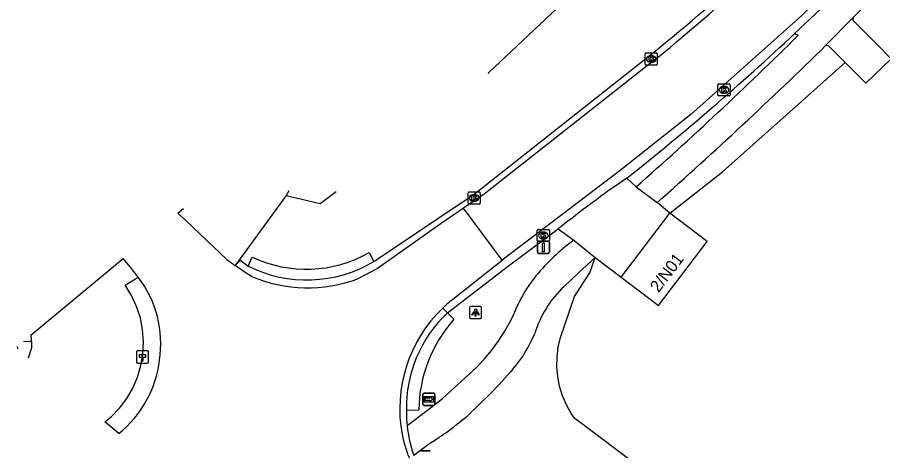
# Model space of a CAD drawing. Extents: x 152881 to 155736, y 382924 to 386919.
# Drawn here: x 152881.3 to 152953.1, y 384938.2 to 384974.1 of the extents above; entities that cross this region are included whole.
import ezdxf

# ---------------------------------------------------------------- set-up
doc = ezdxf.new("R2010")
doc.units = 0
for name, color, linetype in [('IMGEO_Berm_gesloten', 7, 'Continuous'), ('IMGEO_Fietspad_gesloten', 7, 'Continuous'), ('IMGEO_Greppel_droge_sloot', 7, 'Continuous'), ('IMGEO_Groenvoorziening', 7, 'Continuous'), ('IMGEO_Hectometerpaal', 7, 'Continuous'), ('IMGEO_Inrit_open', 7, 'Continuous'), ('IMGEO_Kolk', 7, 'Continuous'), ('IMGEO_Lichtpunt', 7, 'Continuous'), ('IMGEO_Pand', 7, 'Continuous'), ('IMGEO_Pand_nummerreeks', 7, 'Continuous'), ('IMGEO_Rijbaan_lokaal_gesloten', 7, 'Continuous'), ('IMGEO_Rijbaan_lokaal_open', 7, 'Continuous'), ('IMGEO_Sloot', 7, 'Continuous'), ('IMGEO_Verkeersbordpaal', 7, 'Continuous'), ('IMGEO_Wegwijzer', 7, 'Continuous')]:
    doc.layers.add(name, color=color, linetype=linetype)

msp = doc.modelspace()

# ---------------------------------------------------------------- linework, layer by layer
at = {"layer": 'IMGEO_Berm_gesloten'}
for points in [[(152900.494, 384953.465), (152900.84, 384954.217)], [(152910.53, 384954.589), (152910.924, 384953.841)], [(152888.603, 384940.547), (152889.126, 384940.972), (152889.82, 384941.69), (152890.423, 384942.486), (152890.927, 384943.349), (152891.323, 384944.265), (152891.606, 384945.223), (152891.773, 384946.207), (152891.82, 384947.205), (152891.748, 384948.201), (152891.557, 384949.181), (152891.25, 384950.131), (152890.831, 384951.037), (152890.306, 384951.887), (152891.382, 384952.553)], [(152917.573, 384949.062), (152917.038, 384949.591)], [(152913.634, 384941.518), (152914.659, 384941.539)], [(152889.767, 384939.575), (152888.603, 384940.547)]]:
    msp.add_lwpolyline(points, dxfattribs=at)
for centre, radius, start, end in [((152905.327, 384963.724), 10.513, 244.7338, 299.66322), ((152926.146, 384941.415), 11.488, 138.26968, 179.38302)]:
    msp.add_arc(centre, radius, start, end, dxfattribs=at)
at = {"layer": 'IMGEO_Fietspad_gesloten'}
for points in [[(152945.824, 384972.748), (152946.132, 384972.615)], [(152929.279, 384954.181), (152927.904, 384952.921), (152926.712, 384951.78)], [(152922.463, 384944.918), (152922.259, 384944.693), (152921.313, 384943.652), (152920.61, 384942.901), (152918.659, 384941.029)], [(152913.686, 384940.244), (152915.275, 384941.446), (152916.614, 384942.483), (152918.832, 384944.502)], [(152915.788, 384938.903), (152915.471, 384938.681), (152914.235, 384937.764)]]:
    msp.add_lwpolyline(points, dxfattribs=at)
for centre, radius, start, end in [((152770.156, 385151.69), 253.263, 315.47725, 319.44526), ((152727.377, 385193.342), 310.764, 311.3501, 314.74283), ((152680.181, 385245.786), 383.454, 311.53471, 314.39217), ((152937.864, 384941.495), 17.51, 126.25929, 140.39235), ((152932.832, 384945.65), 10.984, 140.35455, 154.21914), ((152932.805, 384945.263), 8.921, 133.07322, 163.00302), ((152908.639, 384955.958), 15.335, 311.66099, 338.85623), ((152913.849, 384952.229), 11.298, 319.6772, 337.31154), ((152902.569, 384959.755), 24.689, 302.37132, 310.6692)]:
    msp.add_arc(centre, radius, start, end, dxfattribs=at)
at = {"layer": 'IMGEO_Greppel_droge_sloot'}
for points in [[(152882.51, 384947.757), (152882.51, 384947.757)], [(152882.52, 384947.238), (152882.51, 384947.757)], [(152881.857, 384947.213), (152882.52, 384947.238)]]:
    msp.add_lwpolyline(points, dxfattribs=at)
at = {"layer": 'IMGEO_Groenvoorziening'}
for points in [[(152920.433, 384969.493), (152927.085, 384975.764)], [(152935.478, 384957.851), (152939.863, 384961.291), (152946.934, 384967.593), (152950.028, 384970.351)], [(152920.46, 384969.417), (152920.433, 384969.493)], [(152903.663, 384959.312), (152906.478, 384958.657), (152907.793, 384959.669)], [(152944.919, 384928.436), (152938.84, 384932.388), (152927.593, 384940.822), (152927.3, 384941.255), (152926.902, 384941.969), (152926.581, 384942.721), (152926.34, 384943.502), (152926.182, 384944.304), (152926.108, 384945.118), (152926.121, 384945.935), (152926.218, 384946.747), (152926.4, 384947.544), (152927.569, 384950.958), (152928.128, 384951.81), (152928.844, 384952.903), (152929.279, 384954.181)], [(152882.51, 384947.757), (152890.131, 384954.102)], [(152882.52, 384947.238), (152882.514, 384946.687), (152882.262, 384945.846)]]:
    msp.add_lwpolyline(points, dxfattribs=at)
at = {"layer": 'IMGEO_Hectometerpaal'}
for p, q in [((152891.238, 384946.348), (152891.238, 384945.507)), ((152891.238, 384946.348), (152891.238, 384945.507)), ((152892.154, 384946.432), (152891.313, 384946.432)), ((152892.154, 384946.432), (152891.313, 384946.432)), ((152892.238, 384945.516), (152892.238, 384946.357)), ((152892.238, 384945.516), (152892.238, 384946.357)), ((152891.322, 384945.432), (152892.163, 384945.432)), ((152891.322, 384945.432), (152892.163, 384945.432))]:
    msp.add_line(p, q, dxfattribs=at)
msp.add_lwpolyline([(152891.763, 384945.576), (152891.703, 384945.576), (152891.703, 384945.881), (152891.483, 384945.881), (152891.483, 384946.15), (152891.983, 384946.15), (152891.983, 384945.881), (152891.763, 384945.881), (152891.763, 384945.576)], dxfattribs=at)
for centre, start, end in [((152891.316, 384946.354), 92.4484, 184.28452), ((152891.316, 384946.354), 92.4484, 184.28452), ((152892.16, 384946.354), 2.4484, 94.28452), ((152892.16, 384946.354), 2.4484, 94.28452), ((152891.316, 384945.51), 182.4484, 274.28452), ((152891.316, 384945.51), 182.4484, 274.28452), ((152892.16, 384945.51), 272.4484, 4.28452), ((152892.16, 384945.51), 272.4484, 4.28452)]:
    msp.add_arc(centre, 0.0779, start, end, dxfattribs=at)
at = {"layer": 'IMGEO_Inrit_open'}
for points in [[(152903.663, 384959.312), (152899.417, 384953.516)], [(152903.887, 384959.703), (152903.663, 384959.312)], [(152894.658, 384957.871), (152895.126, 384958.261)]]:
    msp.add_lwpolyline(points, dxfattribs=at)
at = {"layer": 'IMGEO_Kolk'}
for p, q in [((152933.438, 384970.22), (152933.438, 384971.072)), ((152933.513, 384971.146), (152934.365, 384971.146)), ((152933.926, 384970.926), (152933.951, 384970.926)), ((152934.439, 384971.072), (152934.439, 384970.22)), ((152934.365, 384970.146), (152933.513, 384970.146)), ((152933.949, 384970.366), (152933.924, 384970.366)), ((152939.475, 384967.66), (152939.475, 384968.512)), ((152939.55, 384968.586), (152940.402, 384968.586)), ((152940.476, 384968.512), (152940.476, 384967.66)), ((152939.986, 384967.806), (152939.961, 384967.806)), ((152939.963, 384968.366), (152939.988, 384968.366)), ((152940.402, 384967.586), (152939.55, 384967.586)), ((152918.744, 384958.694), (152918.744, 384959.546)), ((152918.819, 384959.62), (152919.671, 384959.62)), ((152919.232, 384959.4), (152919.257, 384959.4)), ((152919.745, 384959.546), (152919.745, 384958.694)), ((152919.671, 384958.62), (152918.819, 384958.62)), ((152919.255, 384958.84), (152919.23, 384958.84)), ((152924.488, 384955.58), (152924.488, 384956.432)), ((152924.563, 384956.506), (152925.415, 384956.506)), ((152925.489, 384956.432), (152925.489, 384955.58)), ((152924.999, 384955.726), (152924.974, 384955.726)), ((152924.976, 384956.286), (152925.001, 384956.286)), ((152925.415, 384955.506), (152924.563, 384955.506))]:
    msp.add_line(p, q, dxfattribs=at)
for points in [[(152933.438, 384970.22), (152933.438, 384971.072)], [(152933.513, 384971.146), (152934.365, 384971.146)], [(152933.759, 384970.846), (152933.882, 384970.846), (152933.882, 384970.695), (152934.012, 384970.846), (152934.176, 384970.846), (152934.03, 384970.695), (152934.183, 384970.446), (152934.031, 384970.446), (152933.946, 384970.61), (152933.882, 384970.543), (152933.882, 384970.446), (152933.759, 384970.446), (152933.759, 384970.846)], [(152934.439, 384971.072), (152934.439, 384970.22)], [(152934.365, 384970.146), (152933.513, 384970.146)], [(152939.475, 384967.66), (152939.475, 384968.512)], [(152939.55, 384968.586), (152940.402, 384968.586)], [(152940.476, 384968.512), (152940.476, 384967.66)], [(152939.796, 384968.286), (152939.919, 384968.286), (152939.919, 384968.135), (152940.049, 384968.286), (152940.213, 384968.286), (152940.067, 384968.135), (152940.22, 384967.886), (152940.068, 384967.886), (152939.983, 384968.05), (152939.919, 384967.983), (152939.919, 384967.886), (152939.796, 384967.886), (152939.796, 384968.286)], [(152940.402, 384967.586), (152939.55, 384967.586)], [(152918.744, 384958.694), (152918.744, 384959.546)], [(152918.819, 384959.62), (152919.671, 384959.62)], [(152919.065, 384959.32), (152919.188, 384959.32), (152919.188, 384959.169), (152919.318, 384959.32), (152919.482, 384959.32), (152919.336, 384959.169), (152919.489, 384958.92), (152919.337, 384958.92), (152919.252, 384959.084), (152919.188, 384959.017), (152919.188, 384958.92), (152919.065, 384958.92), (152919.065, 384959.32)], [(152919.745, 384959.546), (152919.745, 384958.694)], [(152919.671, 384958.62), (152918.819, 384958.62)], [(152924.488, 384955.58), (152924.488, 384956.432)], [(152924.563, 384956.506), (152925.415, 384956.506)], [(152925.489, 384956.432), (152925.489, 384955.58)], [(152924.809, 384956.206), (152924.932, 384956.206), (152924.932, 384956.055), (152925.062, 384956.206), (152925.226, 384956.206), (152925.08, 384956.055), (152925.233, 384955.806), (152925.081, 384955.806), (152924.996, 384955.97), (152924.932, 384955.903), (152924.932, 384955.806), (152924.809, 384955.806), (152924.809, 384956.206)], [(152925.415, 384955.506), (152924.563, 384955.506)]]:
    msp.add_lwpolyline(points, dxfattribs=at)
for centre, start, end in [((152933.515, 384971.07), 91.55205, 178.44795), ((152933.515, 384971.07), 91.55205, 178.44795), ((152934.363, 384971.07), 1.55205, 88.44795), ((152934.363, 384971.07), 1.55205, 88.44795), ((152933.515, 384970.222), 181.55205, 268.44795), ((152933.515, 384970.222), 181.55205, 268.44795), ((152934.363, 384970.222), 271.55205, 358.44795), ((152934.363, 384970.222), 271.55205, 358.44795), ((152939.552, 384968.51), 91.55205, 178.44795), ((152939.552, 384968.51), 91.55205, 178.44795), ((152940.4, 384968.51), 1.55205, 88.44795), ((152940.4, 384968.51), 1.55205, 88.44795), ((152939.552, 384967.662), 181.55205, 268.44795), ((152939.552, 384967.662), 181.55205, 268.44795), ((152940.4, 384967.662), 271.55205, 358.44795), ((152940.4, 384967.662), 271.55205, 358.44795), ((152918.821, 384959.544), 91.55205, 178.44795), ((152918.821, 384959.544), 91.55205, 178.44795), ((152919.669, 384959.544), 1.55205, 88.44795), ((152919.669, 384959.544), 1.55205, 88.44795), ((152918.821, 384958.696), 181.55205, 268.44795), ((152918.821, 384958.696), 181.55205, 268.44795), ((152919.669, 384958.696), 271.55205, 358.44795), ((152919.669, 384958.696), 271.55205, 358.44795), ((152924.565, 384956.43), 91.55205, 178.44795), ((152924.565, 384956.43), 91.55205, 178.44795), ((152925.413, 384956.43), 1.55205, 88.44795), ((152925.413, 384956.43), 1.55205, 88.44795), ((152924.565, 384955.582), 181.55205, 268.44795), ((152924.565, 384955.582), 181.55205, 268.44795), ((152925.413, 384955.582), 271.55205, 358.44795), ((152925.413, 384955.582), 271.55205, 358.44795)]:
    msp.add_arc(centre, 0.0765, start, end, dxfattribs=at)
for centre, major_axis, ratio, start_param, end_param in [((152933.925, 384970.646), (-0.387, 0.002), 0.722429, 4.712389, 7.853982), ((152933.95, 384970.646), (-0.39, 0.002), 0.717154, 1.570796, 4.712389), ((152939.962, 384968.086), (-0.387, 0.002), 0.722429, 4.712389, 7.853982), ((152939.987, 384968.086), (-0.39, 0.002), 0.717154, 1.570796, 4.712389), ((152919.231, 384959.12), (-0.387, 0.002), 0.722429, 4.712389, 7.853982), ((152919.256, 384959.12), (-0.39, 0.002), 0.717154, 1.570796, 4.712389), ((152924.975, 384956.006), (-0.387, 0.002), 0.722429, 4.712389, 7.853982), ((152925, 384956.006), (-0.39, 0.002), 0.717154, 1.570796, 4.712389)]:
    msp.add_ellipse(centre, major_axis=major_axis, ratio=ratio, start_param=start_param, end_param=end_param, dxfattribs=at)
at = {"layer": 'IMGEO_Lichtpunt'}
for p, q in [((152918.863, 384950.031), (152918.863, 384949.224)), ((152918.863, 384950.031), (152918.863, 384949.224)), ((152919.765, 384950.126), (152918.957, 384950.126)), ((152919.765, 384950.126), (152918.957, 384950.126)), ((152919.859, 384949.224), (152919.859, 384950.031)), ((152919.859, 384949.224), (152919.859, 384950.031)), ((152918.957, 384949.13), (152919.765, 384949.13)), ((152918.957, 384949.13), (152919.765, 384949.13))]:
    msp.add_line(p, q, dxfattribs=at)
for points in [[(152919.237, 384949.695), (152919.276, 384949.667), (152919.088, 384949.405), (152919.05, 384949.432), (152919.237, 384949.695)], [(152919.339, 384949.647), (152919.386, 384949.647), (152919.386, 384949.325), (152919.339, 384949.325), (152919.339, 384949.647)], [(152919.449, 384949.667), (152919.487, 384949.694), (152919.674, 384949.432), (152919.635, 384949.404), (152919.449, 384949.667)]]:
    msp.add_lwpolyline(points, dxfattribs=at)
msp.add_circle((152919.362, 384949.829), 0.0994, dxfattribs=at)
for centre, start, end in [((152918.957, 384950.031), 90, 180), ((152918.957, 384950.031), 90, 180), ((152919.765, 384950.031), 0, 90), ((152919.765, 384950.031), 0, 90), ((152918.957, 384949.224), 180, 270), ((152918.957, 384949.224), 180, 270), ((152919.765, 384949.224), 270, 0), ((152919.765, 384949.224), 270, 360)]:
    msp.add_arc(centre, 0.0946, start, end, dxfattribs=at)
at = {"layer": 'IMGEO_Pand'}
for points in [[(152931.439, 384952.54), (152935.478, 384957.851)], [(152931.439, 384952.54), (152934.539, 384950.19), (152938.57, 384955.499), (152935.478, 384957.851)]]:
    msp.add_lwpolyline(points, dxfattribs=at)
at = {"layer": 'IMGEO_Rijbaan_lokaal_gesloten'}
for points in [[(152985.658, 385021.458), (152985.588, 385021.361), (152976.729, 385009.189), (152967.34, 384996.77), (152960.992, 384989.193), (152957.232, 384984.967), (152949.587, 384977.419), (152946.43, 384974.266), (152937.222, 384966.042), (152931.359, 384961.408), (152921.577, 384953.958)], [(152910.924, 384953.841), (152916.225, 384957.419), (152918.078, 384958.671), (152919.016, 384959.272), (152919.782, 384959.841), (152934.028, 384971.097)], [(152934.413, 384970.705), (152920.087, 384959.424), (152918.374, 384958.267)], [(152894.658, 384957.871), (152895.325, 384957.243), (152898.734, 384954.012), (152899.417, 384953.516)], [(152894.658, 384957.871), (152894.658, 384957.871)], [(152918.374, 384958.267), (152916.505, 384957.005), (152911.22, 384953.262), (152909.594, 384952.411)], [(152921.577, 384953.958), (152918.374, 384958.267)], [(152891.382, 384952.553), (152890.737, 384953.389), (152890.131, 384954.102)], [(152899.417, 384953.516), (152899.873, 384953.949), (152900.494, 384953.465)], [(152900.781, 384952.608), (152900.251, 384952.936), (152899.417, 384953.516)], [(152917.332, 384950.608), (152921.577, 384953.958)]]:
    msp.add_lwpolyline(points, dxfattribs=at)
for centre, radius, start, end in [((152792.046, 385145.43), 224.836, 309.16045, 314.98437), ((152765.646, 385174.071), 264.272, 309.68816, 314.60274), ((152905.363, 384963.256), 10.935, 243.56036, 300.56886), ((152884.201, 384947.047), 9.049, 351.23339, 37.47654), ((152905.439, 384963.777), 12.102, 247.36001, 290.07891), ((152925.13, 384941.139), 12.266, 129.47294, 133.82479), ((152924.711, 384941.607), 11.639, 133.9321, 190.38943), ((152883.974, 384946.768), 9.236, 308.84644, 353.15939), ((152924.341, 384941.867), 11.326, 192.01942, 214.52076)]:
    msp.add_arc(centre, radius, start, end, dxfattribs=at)
at = {"layer": 'IMGEO_Rijbaan_lokaal_open'}
for points in [[(152945.824, 384972.748), (152948.903, 384975.656), (152949.991, 384976.683)], [(152950.725, 384974.104), (152948.432, 384971.782)], [(152950.028, 384970.351), (152951.749, 384968.654), (152953.835, 384970.67), (152952.592, 384971.926), (152950.689, 384973.85), (152950.725, 384974.104)], [(152948.432, 384971.782), (152948.603, 384971.756), (152950.028, 384970.351)], [(152932.686, 384960.056), (152931.914, 384960.767)], [(152932.686, 384960.056), (152934.439, 384958.75)], [(152935.478, 384957.851), (152934.439, 384958.75)], [(152917.038, 384949.591), (152921.384, 384952.942), (152921.994, 384953.396), (152926.228, 384956.548)], [(152926.228, 384956.548), (152927.508, 384955.614)], [(152927.508, 384955.614), (152929.279, 384954.181)], [(152929.279, 384954.181), (152931.439, 384952.54)], [(152916.636, 384949.989), (152917.038, 384949.591)]]:
    msp.add_lwpolyline(points, dxfattribs=at)
for centre, radius, start, end in [((152795.031, 385133.754), 220.594, 308.35422, 313.12392), ((152980.061, 384889.938), 85.644, 124.2063, 128.94437), ((152924.34, 384941.758), 10.709, 132.99012, 181.2842), ((152924.323, 384941.316), 10.691, 178.91872, 185.7559), ((152924.392, 384941.313), 10.759, 185.7032, 199.26144)]:
    msp.add_arc(centre, radius, start, end, dxfattribs=at)
at = {"layer": 'IMGEO_Sloot'}
msp.add_lwpolyline([(152881.349, 384946.791), (152881.356, 384946.603)], dxfattribs=at)
at = {"layer": 'IMGEO_Verkeersbordpaal'}
for p, q in [((152924.495, 384954.626), (152924.495, 384955.426)), ((152924.495, 384955.426), (152924.495, 384954.626)), ((152924.595, 384955.526), (152925.385, 384955.526)), ((152925.385, 384955.526), (152924.595, 384955.526)), ((152925.485, 384955.426), (152925.485, 384954.626)), ((152925.485, 384954.626), (152925.485, 384955.426)), ((152925.385, 384954.526), (152924.595, 384954.526)), ((152924.595, 384954.526), (152925.385, 384954.526)), ((152914.807, 384938.162), (152915.597, 384938.162)), ((152915.597, 384938.162), (152914.807, 384938.162))]:
    msp.add_line(p, q, dxfattribs=at)
msp.add_lwpolyline([(152924.915, 384955.401), (152925.065, 384955.401), (152925.065, 384954.651), (152924.915, 384954.651), (152924.915, 384955.401)], dxfattribs=at)
for centre, start, end in [((152924.595, 384955.426), 90, 180), ((152924.595, 384955.426), 90, 180), ((152925.385, 384955.426), 0, 90), ((152925.385, 384955.426), 360, 90), ((152924.595, 384954.626), 180, 270), ((152924.595, 384954.626), 180, 270), ((152925.385, 384954.626), 270, 0), ((152925.385, 384954.626), 270, 0)]:
    msp.add_arc(centre, 0.1, start, end, dxfattribs=at)
at = {"layer": 'IMGEO_Wegwijzer'}
for p, q in [((152914.989, 384942.022), (152914.989, 384942.822)), ((152914.989, 384942.822), (152914.989, 384942.022)), ((152915.089, 384942.922), (152915.879, 384942.922)), ((152915.879, 384942.922), (152915.089, 384942.922)), ((152915.979, 384942.822), (152915.979, 384942.022)), ((152915.979, 384942.022), (152915.979, 384942.822)), ((152915.879, 384941.922), (152915.089, 384941.922)), ((152915.089, 384941.922), (152915.879, 384941.922))]:
    msp.add_line(p, q, dxfattribs=at)
for points in [[(152915.09, 384942.654), (152915.878, 384942.654), (152915.878, 384942.19), (152915.09, 384942.19), (152915.09, 384942.654)], [(152915.155, 384942.506), (152915.155, 384942.422), (152915.155, 384942.338), (152915.566, 384942.338), (152915.566, 384942.255), (152915.813, 384942.422), (152915.566, 384942.589), (152915.566, 384942.506), (152915.155, 384942.506)]]:
    msp.add_lwpolyline(points, dxfattribs=at)
for centre, start, end in [((152915.089, 384942.822), 90, 180), ((152915.089, 384942.822), 90, 180), ((152915.879, 384942.822), 0, 90), ((152915.879, 384942.822), 360, 90), ((152915.089, 384942.022), 180, 270), ((152915.089, 384942.022), 180, 270), ((152915.879, 384942.022), 270, 0), ((152915.879, 384942.022), 270, 0)]:
    msp.add_arc(centre, 0.1, start, end, dxfattribs=at)

# ---------------------------------------------------------------- texts
at = {"layer": 'IMGEO_Pand_nummerreeks'}
msp.add_text('2/N01', height=1, rotation=52.85801, dxfattribs=at).set_placement((152934.543, 384951.212))

doc.saveas('drawing.dxf')
